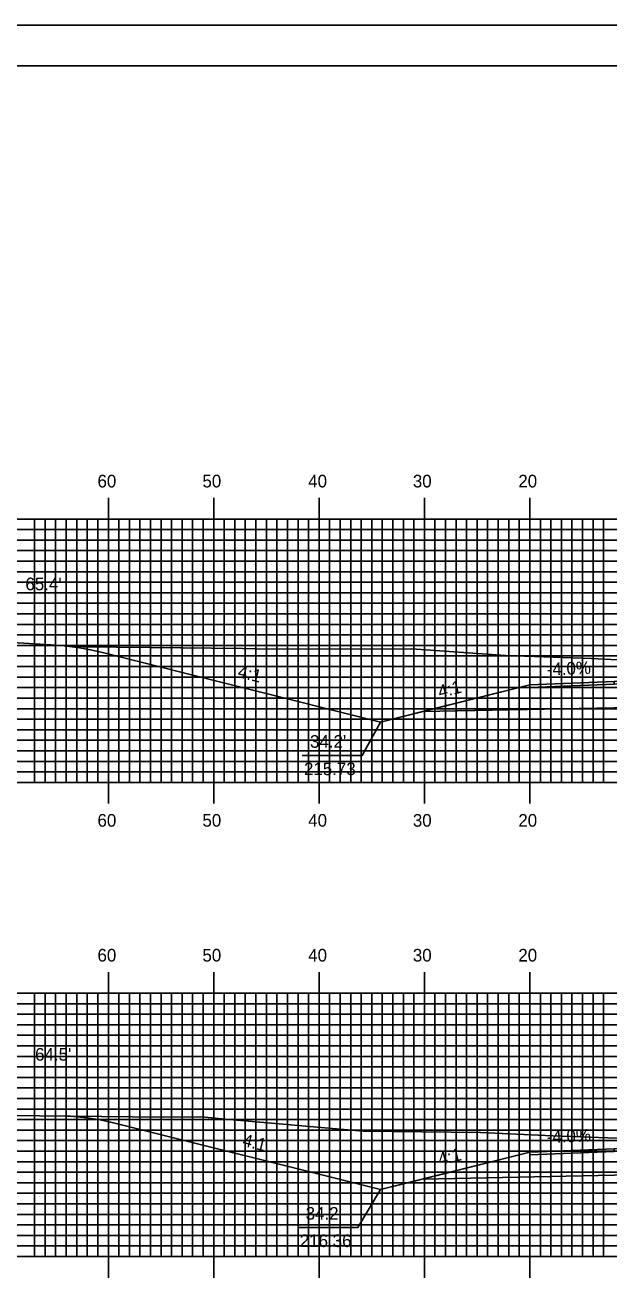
# Model space of a CAD drawing. Extents: x 1820031 to 1820374, y 442591 to 442811.
# Drawn here: x 1820128.8 to 1820184.2, y 442691.2 to 442810.5 of the extents above; entities that cross this region are included whole.
import ezdxf

# ---------------------------------------------------------------- set-up
doc = ezdxf.new("R2010")
doc.units = 0
for name, color, linetype in [('ANNOTATION', 7, 'Continuous'), ('BORDER', 7, 'Continuous'), ('D_Roadway_Centerline', 7, 'Continuous'), ('D_Roadway_Edge_Shoulder', 7, 'Continuous'), ('D_Roadway_SlopeLines', 7, 'Continuous'), ('D_Roadway_SubGrade', 7, 'Continuous'), ('D_Text_Standard', 7, 'Continuous'), ('H_V ANNOTATION', 7, 'Continuous'), ('MAJOR', 7, 'Continuous'), ('MINOR', 7, 'Continuous'), ('PLOT BOUNDARY', 7, 'Continuous'), ('S_Roadway_Centerline', 7, 'Continuous')]:
    doc.layers.add(name, color=color, linetype=linetype)

msp = doc.modelspace()

# ---------------------------------------------------------------- linework, layer by layer
at = {"layer": 'ANNOTATION'}
for points in [[(1820155.09, 442741.23), (1820160.79, 442741.23), (1820162.52, 442744.4)], [(1820154.69, 442696.44), (1820160.38, 442696.44), (1820162.52, 442700.02)]]:
    msp.add_lwpolyline(points, dxfattribs=at)
at = {"layer": 'BORDER'}
msp.add_lwpolyline([(1820047.09, 442596.67), (1820367.09, 442596.67), (1820367.09, 442806.67), (1820047.09, 442806.67)], close=True, dxfattribs=at)
at = {"layer": 'D_Roadway_Centerline'}
for points in [[(1820131.25, 442751.74), (1820132.5, 442751.64), (1820133.75, 442751.47), (1820135, 442751.25), (1820136.25, 442750.96), (1820162.52, 442744.4), (1820166.52, 442745.4), (1820176.69, 442747.94), (1820184.69, 442748.26), (1820196.69, 442748.5), (1820208.69, 442748.26), (1820217.17, 442747.92), (1820227.3, 442745.39), (1820231.3, 442744.39), (1820242.74, 442747.25), (1820243.99, 442747.52), (1820245.24, 442747.71), (1820246.49, 442747.82), (1820247.74, 442747.85)], [(1820132.17, 442707.01), (1820133.42, 442706.96), (1820134.67, 442706.83), (1820135.92, 442706.63), (1820137.17, 442706.36), (1820162.52, 442700.02), (1820166.52, 442701.02), (1820176.69, 442703.57), (1820184.69, 442703.89), (1820196.69, 442704.13), (1820208.69, 442703.89), (1820216.69, 442703.57), (1820226.86, 442701.02), (1820230.86, 442700.02), (1820239.1, 442702.08), (1820240.35, 442702.35), (1820241.6, 442702.54), (1820242.85, 442702.64), (1820244.1, 442702.65)]]:
    msp.add_lwpolyline(points, dxfattribs=at)
at = {"layer": 'D_Roadway_Edge_Shoulder'}
for points in [[(1820184.69, 442748.26), (1820176.69, 442747.94), (1820176.69, 442747.69), (1820184.69, 442748.01)], [(1820184.69, 442703.89), (1820176.69, 442703.57), (1820176.69, 442703.32), (1820184.69, 442703.64)]]:
    msp.add_lwpolyline(points, close=True, dxfattribs=at)
at = {"layer": 'D_Roadway_SlopeLines'}
for points in [[(1820162.52, 442744.4), (1820136.25, 442750.96), (1820135, 442751.25), (1820133.75, 442751.47), (1820132.5, 442751.64), (1820131.25, 442751.74)], [(1820176.69, 442747.94), (1820162.52, 442744.4)], [(1820162.52, 442700.02), (1820137.17, 442706.36), (1820135.92, 442706.63), (1820134.67, 442706.83), (1820133.42, 442706.96), (1820132.17, 442707.01)], [(1820176.69, 442703.57), (1820162.52, 442700.02)]]:
    msp.add_lwpolyline(points, dxfattribs=at)
at = {"layer": 'D_Roadway_SubGrade'}
for points in [[(1820184.69, 442745.76), (1820166.52, 442745.4), (1820176.69, 442747.94), (1820176.69, 442747.69), (1820184.69, 442748.01), (1820196.69, 442748.25), (1820208.69, 442748.01), (1820217.17, 442747.67), (1820217.17, 442747.92), (1820227.3, 442745.39), (1820208.69, 442745.76), (1820196.69, 442746)], [(1820184.69, 442701.39), (1820166.52, 442701.02), (1820176.69, 442703.57), (1820176.69, 442703.32), (1820184.69, 442703.64), (1820196.69, 442703.88), (1820208.69, 442703.64), (1820216.69, 442703.32), (1820216.69, 442703.57), (1820226.86, 442701.02), (1820208.69, 442701.39), (1820196.69, 442701.63)]]:
    msp.add_lwpolyline(points, close=True, dxfattribs=at)
at = {"layer": 'MAJOR'}
for p, q in [((1820136.69, 442765.67), (1820136.69, 442763.67)), ((1820146.69, 442765.67), (1820146.69, 442763.67)), ((1820156.69, 442765.67), (1820156.69, 442763.67)), ((1820166.69, 442765.67), (1820166.69, 442763.67)), ((1820176.69, 442765.67), (1820176.69, 442763.67)), ((1820056.69, 442763.67), (1820336.69, 442763.67)), ((1820056.69, 442763.67), (1820336.69, 442763.67)), ((1820136.69, 442738.67), (1820136.69, 442763.67)), ((1820146.69, 442738.67), (1820146.69, 442763.67)), ((1820156.69, 442738.67), (1820156.69, 442763.67)), ((1820166.69, 442738.67), (1820166.69, 442763.67)), ((1820176.69, 442738.67), (1820176.69, 442763.67)), ((1820056.69, 442758.67), (1820336.69, 442758.67)), ((1820056.69, 442753.67), (1820336.69, 442753.67)), ((1820056.69, 442748.67), (1820336.69, 442748.67)), ((1820056.69, 442743.67), (1820336.69, 442743.67)), ((1820056.69, 442738.67), (1820336.69, 442738.67)), ((1820056.69, 442738.67), (1820336.69, 442738.67)), ((1820136.69, 442736.66), (1820136.69, 442738.67)), ((1820146.69, 442736.66), (1820146.69, 442738.67)), ((1820156.69, 442736.66), (1820156.69, 442738.67)), ((1820166.69, 442736.66), (1820166.69, 442738.67)), ((1820176.69, 442736.66), (1820176.69, 442738.67)), ((1820136.69, 442720.67), (1820136.69, 442718.67)), ((1820146.69, 442720.67), (1820146.69, 442718.67)), ((1820156.69, 442720.67), (1820156.69, 442718.67)), ((1820166.69, 442720.67), (1820166.69, 442718.67)), ((1820176.69, 442720.67), (1820176.69, 442718.67)), ((1820056.69, 442718.67), (1820336.69, 442718.67)), ((1820056.69, 442718.67), (1820336.69, 442718.67)), ((1820136.69, 442693.67), (1820136.69, 442718.67)), ((1820146.69, 442693.67), (1820146.69, 442718.67)), ((1820156.69, 442693.67), (1820156.69, 442718.67)), ((1820166.69, 442693.67), (1820166.69, 442718.67)), ((1820176.69, 442693.67), (1820176.69, 442718.67)), ((1820056.69, 442713.67), (1820336.69, 442713.67)), ((1820056.69, 442708.67), (1820336.69, 442708.67)), ((1820056.69, 442703.67), (1820336.69, 442703.67)), ((1820056.69, 442698.67), (1820336.69, 442698.67)), ((1820056.69, 442693.67), (1820336.69, 442693.67)), ((1820056.69, 442693.67), (1820336.69, 442693.67)), ((1820136.69, 442691.66), (1820136.69, 442693.67)), ((1820146.69, 442691.66), (1820146.69, 442693.67)), ((1820156.69, 442691.66), (1820156.69, 442693.67)), ((1820166.69, 442691.66), (1820166.69, 442693.67)), ((1820176.69, 442691.66), (1820176.69, 442693.67))]:
    msp.add_line(p, q, dxfattribs=at)
at = {"layer": 'MINOR'}
for p, q in [((1820129.69, 442738.67), (1820129.69, 442763.67)), ((1820130.69, 442738.67), (1820130.69, 442763.67)), ((1820131.69, 442738.67), (1820131.69, 442763.67)), ((1820132.69, 442738.67), (1820132.69, 442763.67)), ((1820133.69, 442738.67), (1820133.69, 442763.67)), ((1820134.69, 442738.67), (1820134.69, 442763.67)), ((1820135.69, 442738.67), (1820135.69, 442763.67)), ((1820137.69, 442738.67), (1820137.69, 442763.67)), ((1820138.69, 442738.67), (1820138.69, 442763.67)), ((1820139.69, 442738.67), (1820139.69, 442763.67)), ((1820140.69, 442738.67), (1820140.69, 442763.67)), ((1820141.69, 442738.67), (1820141.69, 442763.67)), ((1820142.69, 442738.67), (1820142.69, 442763.67)), ((1820143.69, 442738.67), (1820143.69, 442763.67)), ((1820144.69, 442738.67), (1820144.69, 442763.67)), ((1820145.69, 442738.67), (1820145.69, 442763.67)), ((1820147.69, 442738.67), (1820147.69, 442763.67)), ((1820148.69, 442738.67), (1820148.69, 442763.67)), ((1820149.69, 442738.67), (1820149.69, 442763.67)), ((1820150.69, 442738.67), (1820150.69, 442763.67)), ((1820151.69, 442738.67), (1820151.69, 442763.67)), ((1820152.69, 442738.67), (1820152.69, 442763.67)), ((1820153.69, 442738.67), (1820153.69, 442763.67)), ((1820154.69, 442738.67), (1820154.69, 442763.67)), ((1820155.69, 442738.67), (1820155.69, 442763.67)), ((1820157.69, 442738.67), (1820157.69, 442763.67)), ((1820158.69, 442738.67), (1820158.69, 442763.67)), ((1820159.69, 442738.67), (1820159.69, 442763.67)), ((1820160.69, 442738.67), (1820160.69, 442763.67)), ((1820161.69, 442738.67), (1820161.69, 442763.67)), ((1820162.69, 442738.67), (1820162.69, 442763.67)), ((1820163.69, 442738.67), (1820163.69, 442763.67)), ((1820164.69, 442738.67), (1820164.69, 442763.67)), ((1820165.69, 442738.67), (1820165.69, 442763.67)), ((1820167.69, 442738.67), (1820167.69, 442763.67)), ((1820168.69, 442738.67), (1820168.69, 442763.67)), ((1820169.69, 442738.67), (1820169.69, 442763.67)), ((1820170.69, 442738.67), (1820170.69, 442763.67)), ((1820171.69, 442738.67), (1820171.69, 442763.67)), ((1820172.69, 442738.67), (1820172.69, 442763.67)), ((1820173.69, 442738.67), (1820173.69, 442763.67)), ((1820174.69, 442738.67), (1820174.69, 442763.67)), ((1820175.69, 442738.67), (1820175.69, 442763.67)), ((1820177.69, 442738.67), (1820177.69, 442763.67)), ((1820178.69, 442738.67), (1820178.69, 442763.67)), ((1820179.69, 442738.67), (1820179.69, 442763.67)), ((1820180.69, 442738.67), (1820180.69, 442763.67)), ((1820181.69, 442738.67), (1820181.69, 442763.67)), ((1820182.69, 442738.67), (1820182.69, 442763.67)), ((1820183.69, 442738.67), (1820183.69, 442763.67)), ((1820056.69, 442762.67), (1820336.69, 442762.67)), ((1820056.69, 442761.67), (1820336.69, 442761.67)), ((1820056.69, 442760.67), (1820336.69, 442760.67)), ((1820056.69, 442759.67), (1820336.69, 442759.67)), ((1820056.69, 442757.67), (1820336.69, 442757.67)), ((1820056.69, 442756.67), (1820336.69, 442756.67)), ((1820056.69, 442755.67), (1820336.69, 442755.67)), ((1820056.69, 442754.67), (1820336.69, 442754.67)), ((1820056.69, 442752.67), (1820336.69, 442752.67)), ((1820056.69, 442751.67), (1820336.69, 442751.67)), ((1820056.69, 442750.67), (1820336.69, 442750.67)), ((1820056.69, 442749.67), (1820336.69, 442749.67)), ((1820056.69, 442747.67), (1820336.69, 442747.67)), ((1820056.69, 442746.67), (1820336.69, 442746.67)), ((1820056.69, 442745.67), (1820336.69, 442745.67)), ((1820056.69, 442744.67), (1820336.69, 442744.67)), ((1820056.69, 442742.67), (1820336.69, 442742.67)), ((1820056.69, 442741.67), (1820336.69, 442741.67)), ((1820056.69, 442740.67), (1820336.69, 442740.67)), ((1820056.69, 442739.67), (1820336.69, 442739.67)), ((1820129.69, 442693.67), (1820129.69, 442718.67)), ((1820130.69, 442693.67), (1820130.69, 442718.67)), ((1820131.69, 442693.67), (1820131.69, 442718.67)), ((1820132.69, 442693.67), (1820132.69, 442718.67)), ((1820133.69, 442693.67), (1820133.69, 442718.67)), ((1820134.69, 442693.67), (1820134.69, 442718.67)), ((1820135.69, 442693.67), (1820135.69, 442718.67)), ((1820137.69, 442693.67), (1820137.69, 442718.67)), ((1820138.69, 442693.67), (1820138.69, 442718.67)), ((1820139.69, 442693.67), (1820139.69, 442718.67)), ((1820140.69, 442693.67), (1820140.69, 442718.67)), ((1820141.69, 442693.67), (1820141.69, 442718.67)), ((1820142.69, 442693.67), (1820142.69, 442718.67)), ((1820143.69, 442693.67), (1820143.69, 442718.67)), ((1820144.69, 442693.67), (1820144.69, 442718.67)), ((1820145.69, 442693.67), (1820145.69, 442718.67)), ((1820147.69, 442693.67), (1820147.69, 442718.67)), ((1820148.69, 442693.67), (1820148.69, 442718.67)), ((1820149.69, 442693.67), (1820149.69, 442718.67)), ((1820150.69, 442693.67), (1820150.69, 442718.67)), ((1820151.69, 442693.67), (1820151.69, 442718.67)), ((1820152.69, 442693.67), (1820152.69, 442718.67)), ((1820153.69, 442693.67), (1820153.69, 442718.67)), ((1820154.69, 442693.67), (1820154.69, 442718.67)), ((1820155.69, 442693.67), (1820155.69, 442718.67)), ((1820157.69, 442693.67), (1820157.69, 442718.67)), ((1820158.69, 442693.67), (1820158.69, 442718.67)), ((1820159.69, 442693.67), (1820159.69, 442718.67)), ((1820160.69, 442693.67), (1820160.69, 442718.67)), ((1820161.69, 442693.67), (1820161.69, 442718.67)), ((1820162.69, 442693.67), (1820162.69, 442718.67)), ((1820163.69, 442693.67), (1820163.69, 442718.67)), ((1820164.69, 442693.67), (1820164.69, 442718.67)), ((1820165.69, 442693.67), (1820165.69, 442718.67)), ((1820167.69, 442693.67), (1820167.69, 442718.67)), ((1820168.69, 442693.67), (1820168.69, 442718.67)), ((1820169.69, 442693.67), (1820169.69, 442718.67)), ((1820170.69, 442693.67), (1820170.69, 442718.67)), ((1820171.69, 442693.67), (1820171.69, 442718.67)), ((1820172.69, 442693.67), (1820172.69, 442718.67)), ((1820173.69, 442693.67), (1820173.69, 442718.67)), ((1820174.69, 442693.67), (1820174.69, 442718.67)), ((1820175.69, 442693.67), (1820175.69, 442718.67)), ((1820177.69, 442693.67), (1820177.69, 442718.67)), ((1820178.69, 442693.67), (1820178.69, 442718.67)), ((1820179.69, 442693.67), (1820179.69, 442718.67)), ((1820180.69, 442693.67), (1820180.69, 442718.67)), ((1820181.69, 442693.67), (1820181.69, 442718.67)), ((1820182.69, 442693.67), (1820182.69, 442718.67)), ((1820183.69, 442693.67), (1820183.69, 442718.67)), ((1820056.69, 442717.67), (1820336.69, 442717.67)), ((1820056.69, 442716.67), (1820336.69, 442716.67)), ((1820056.69, 442715.67), (1820336.69, 442715.67)), ((1820056.69, 442714.67), (1820336.69, 442714.67)), ((1820056.69, 442712.67), (1820336.69, 442712.67)), ((1820056.69, 442711.67), (1820336.69, 442711.67)), ((1820056.69, 442710.67), (1820336.69, 442710.67)), ((1820056.69, 442709.67), (1820336.69, 442709.67)), ((1820056.69, 442707.67), (1820336.69, 442707.67)), ((1820056.69, 442706.67), (1820336.69, 442706.67)), ((1820056.69, 442705.67), (1820336.69, 442705.67)), ((1820056.69, 442704.67), (1820336.69, 442704.67)), ((1820056.69, 442702.67), (1820336.69, 442702.67)), ((1820056.69, 442701.67), (1820336.69, 442701.67)), ((1820056.69, 442700.67), (1820336.69, 442700.67)), ((1820056.69, 442699.67), (1820336.69, 442699.67)), ((1820056.69, 442697.67), (1820336.69, 442697.67)), ((1820056.69, 442696.67), (1820336.69, 442696.67)), ((1820056.69, 442695.67), (1820336.69, 442695.67)), ((1820056.69, 442694.67), (1820336.69, 442694.67))]:
    msp.add_line(p, q, dxfattribs=at)
at = {"layer": 'PLOT BOUNDARY'}
msp.add_lwpolyline([(1820030.9, 442590.55), (1820370.9, 442590.55), (1820370.9, 442810.55), (1820030.9, 442810.55)], close=True, dxfattribs=at)
at = {"layer": 'S_Roadway_Centerline'}
for points in [[(1820056.69, 442754.46), (1820062.03, 442754.36), (1820063.89, 442754.33), (1820065.67, 442754.29), (1820069.06, 442754.43), (1820098.12, 442753.95), (1820113.68, 442752.8), (1820132.79, 442751.65), (1820134.29, 442751.55), (1820140.62, 442751.49), (1820149.41, 442751.38), (1820151.92, 442751.32), (1820165.5, 442751.36), (1820174.38, 442750.71), (1820182.55, 442750.44), (1820197.57, 442749.67), (1820199.21, 442749.66), (1820199.99, 442749.57), (1820203.77, 442749.42), (1820233.29, 442748.15), (1820241.27, 442747.91), (1820249.59, 442747.83), (1820279.36, 442747.36)], [(1820121.31, 442707.11), (1820141.91, 442706.91), (1820145.18, 442706.93), (1820145.84, 442706.89), (1820147.82, 442706.7), (1820160.86, 442705.56), (1820172, 442705.45), (1820178.86, 442705.14), (1820191.06, 442704.67), (1820195.84, 442704.41), (1820198.73, 442704.26), (1820213.19, 442704.07), (1820214.34, 442704), (1820226.03, 442703.01), (1820229.41, 442702.78), (1820234.68, 442702.86), (1820245.62, 442702.62), (1820258.95, 442701.86)]]:
    msp.add_lwpolyline(points, dxfattribs=at)

# ---------------------------------------------------------------- texts
at = {"layer": 'ANNOTATION'}
for s, rotation, p in [('4:1', 345.9638, (1820148.89, 442748.67)), ('-4.0%', 2.2906, (1820178.32, 442748.81)), ('4:1', 14.0362, (1820168.14, 442746.67)), ('4:1', 345.9638, (1820149.35, 442704.18)), ('-4.0%', 2.2906, (1820178.32, 442704.43)), ('4:1', 14.0362, (1820168.14, 442702.29))]:
    msp.add_text(s, height=1.2, rotation=rotation, dxfattribs=at).set_placement(p)
for s, p in [("34.2'", (1820155.83, 442741.96)), ('215.73', (1820155.26, 442739.36)), ("34.2'", (1820155.42, 442697.17)), ('216.36', (1820154.86, 442694.57))]:
    msp.add_text(s, height=1.2, dxfattribs=at).set_placement(p)
at = {"layer": 'D_Text_Standard'}
for s, p in [("65.4'", (1820128.82, 442756.91)), ("64.5'", (1820129.74, 442712.26))]:
    msp.add_text(s, height=1.2, dxfattribs=at).set_placement(p)
at = {"layer": 'H_V ANNOTATION'}
for s, p in [('60', (1820135.66, 442766.67)), ('50', (1820145.62, 442766.67)), ('40', (1820155.66, 442766.67)), ('30', (1820165.59, 442766.67)), ('20', (1820175.6, 442766.67)), ('60', (1820135.66, 442734.47)), ('50', (1820145.62, 442734.47)), ('40', (1820155.66, 442734.47)), ('30', (1820165.59, 442734.47)), ('20', (1820175.6, 442734.47)), ('60', (1820135.66, 442721.67)), ('50', (1820145.62, 442721.67)), ('40', (1820155.66, 442721.67)), ('30', (1820165.59, 442721.67)), ('20', (1820175.6, 442721.67))]:
    msp.add_text(s, height=1.2, dxfattribs=at).set_placement(p)

doc.saveas('drawing.dxf')
